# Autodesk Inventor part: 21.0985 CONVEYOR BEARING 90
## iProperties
Created: 2007-07
Part Number: 21.0985 CONVEYOR BEARING 90
Document SubType Name: Modeling
Designer: Andy Moles
Material: Aluminum-6061
Mass: 710.775 g
Surface Area: 731.741 cm^2
Volume: 262.278 cm^3
Density: 2.71 g/cm^3
Author: Andy Moles
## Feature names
1. Extrusion1
2. Extrusion2
3. Hole1
4. Chamfer1
5. Extrusion3
6. Fillet1
7. Extrusion4
8. Extrusion5
9. Mirror1
10. Extrusion6
11. Extrusion7
12. Extrusion8
13. Extrusion9
14. Extrusion10
15. Extrusion11
16. Extrusion12
17. Mirror2
